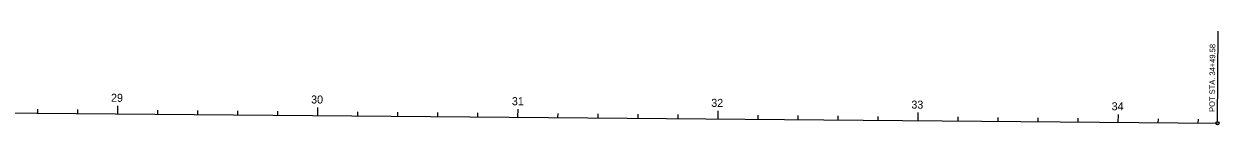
# Model space of a CAD drawing. Extents: x 509738 to 512118, y 1314883 to 1316817.
# Drawn here: x 511521 to 512118, y 1315612 to 1315659 of the extents above; entities that cross this region are included whole.
import ezdxf

# ---------------------------------------------------------------- set-up
doc = ezdxf.new("R2010")
doc.units = 0
for name, color, linetype in [('CLConst_dp', 7, 'Continuous'), ('CurveDataLabel_dp', 7, 'Continuous'), ('StationTicL_dp', 7, 'Continuous'), ('StationTicS_dp', 7, 'Continuous'), ('TextBLStation', 7, 'Continuous')]:
    doc.layers.add(name, color=color, linetype=linetype)

msp = doc.modelspace()

# ---------------------------------------------------------------- linework, layer by layer
at = {"layer": 'CLConst_dp'}
msp.add_line((511105.4, 1315621.62), (512116.98, 1315613.07), dxfattribs=at)
at = {"layer": 'CurveDataLabel_dp'}
msp.add_line((512116.98, 1315613.87), (512117.36, 1315658.89), dxfattribs=at)
msp.add_circle((512116.98, 1315613.07), 0.8, dxfattribs=at)
at = {"layer": 'StationTicL_dp'}
for p, q in [((511567.42, 1315617.72), (511567.45, 1315621.72)), ((511667.41, 1315616.87), (511667.45, 1315620.87)), ((511767.41, 1315616.03), (511767.44, 1315620.03)), ((511867.41, 1315615.18), (511867.44, 1315619.18)), ((511967.4, 1315614.34), (511967.44, 1315618.34)), ((512067.4, 1315613.49), (512067.43, 1315617.49))]:
    msp.add_line(p, q, dxfattribs=at)
at = {"layer": 'StationTicS_dp'}
for p, q in [((511527.42, 1315618.06), (511527.44, 1315620.06)), ((511547.42, 1315617.89), (511547.43, 1315619.89)), ((511587.42, 1315617.55), (511587.43, 1315619.55)), ((511607.42, 1315617.38), (511607.43, 1315619.38)), ((511627.41, 1315617.21), (511627.43, 1315619.21)), ((511647.41, 1315617.04), (511647.43, 1315619.04)), ((511687.41, 1315616.7), (511687.43, 1315618.7)), ((511707.41, 1315616.53), (511707.43, 1315618.53)), ((511727.41, 1315616.36), (511727.43, 1315618.36)), ((511747.41, 1315616.2), (511747.43, 1315618.2)), ((511787.41, 1315615.86), (511787.43, 1315617.86)), ((511807.41, 1315615.69), (511807.43, 1315617.69)), ((511827.41, 1315615.52), (511827.42, 1315617.52)), ((511847.41, 1315615.35), (511847.42, 1315617.35)), ((511887.41, 1315615.01), (511887.42, 1315617.01)), ((511907.4, 1315614.84), (511907.42, 1315616.84)), ((511927.4, 1315614.67), (511927.42, 1315616.67)), ((511947.4, 1315614.5), (511947.42, 1315616.5)), ((511987.4, 1315614.17), (511987.42, 1315616.17)), ((512007.4, 1315614), (512007.42, 1315616)), ((512027.4, 1315613.83), (512027.42, 1315615.83)), ((512047.4, 1315613.66), (512047.42, 1315615.66)), ((512087.4, 1315613.32), (512087.42, 1315615.32)), ((512107.4, 1315613.15), (512107.41, 1315615.15))]:
    msp.add_line(p, q, dxfattribs=at)

# ---------------------------------------------------------------- texts
at = {"layer": 'CurveDataLabel_dp'}
msp.add_text('POT STA. 34+49.58', height=2.8, rotation=89.51549, dxfattribs=at).set_placement((512115.62, 1315618.68))
at = {"layer": 'TextBLStation'}
for s, p in [('29', (511564.04, 1315623.75)), ('30', (511664.04, 1315622.9)), ('31', (511764.35, 1315622.05)), ('32', (511863.98, 1315621.21)), ('33', (511963.98, 1315620.36)), ('34', (512064.06, 1315619.52))]:
    msp.add_text(s, height=4, rotation=359.51549, dxfattribs=at).set_placement(p)

doc.saveas('drawing.dxf')
